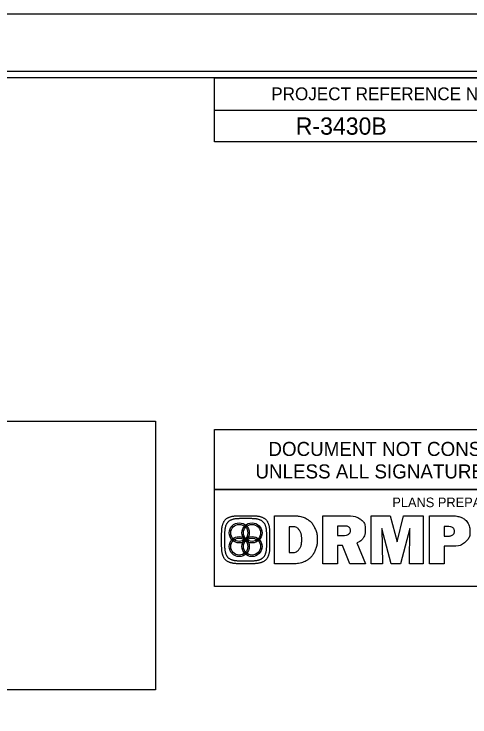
# Model space of a CAD drawing. Extents: x 1252282 to 1252460, y 733735 to 733845.
# Drawn here: x 1252421.03 to 1252438.88, y 733817 to 733844.5 of the extents above; entities that cross this region are included whole.
import ezdxf

# ---------------------------------------------------------------- set-up
doc = ezdxf.new("R2010")
doc.units = 0
for name, color, linetype in [('Default', 7, 'Continuous'), ('Pattern 1', 7, 'Continuous'), ('Pattern 2', 7, 'Continuous'), ('Scratch_Level_0', 7, 'Continuous'), ('Sheet Cutting Line CELL', 7, 'Continuous'), ('Sheet Data Field CELL', 7, 'Continuous'), ('Sheet Plot Border Inside CELL', 7, 'Continuous'), ('Sheet Plot Border Outside CELL', 7, 'Continuous'), ('Sheet Sticker Exception Certification CELL', 7, 'Continuous'), ('Sheet Typical CELL', 7, 'Continuous')]:
    doc.layers.add(name, color=color, linetype=linetype)

msp = doc.modelspace()

# ---------------------------------------------------------------- linework, layer by layer
at = {"layer": 'Default'}
msp.add_lwpolyline([(1252386.483, 733828.578), (1252426.564, 733828.578), (1252426.564, 733818.059), (1252386.483, 733818.059)], close=True, dxfattribs=at)
at = {"layer": 'Pattern 1'}
for p, q in [((1252429.822, 733824.875), (1252430.367, 733824.875)), ((1252435.01, 733822.994), (1252435.01, 733824.873)), ((1252435.01, 733824.873), (1252435.75, 733824.873)), ((1252435.75, 733824.873), (1252436.031, 733823.847)), ((1252436.031, 733823.847), (1252436.279, 733824.873)), ((1252436.279, 733824.873), (1252437.051, 733824.873)), ((1252437.051, 733824.873), (1252437.051, 733822.994)), ((1252430.334, 733824.76), (1252429.856, 733824.76)), ((1252435.796, 733822.994), (1252435.43, 733824.372)), ((1252435.43, 733824.372), (1252435.45, 733822.994)), ((1252436.518, 733824.372), (1252436.16, 733822.994)), ((1252436.509, 733822.994), (1252436.518, 733824.372)), ((1252429.156, 733823.663), (1252429.156, 733824.208)), ((1252429.271, 733824.175), (1252429.271, 733823.697)), ((1252430.919, 733823.697), (1252430.919, 733824.175)), ((1252431.034, 733824.208), (1252431.034, 733823.663)), ((1252430.367, 733822.997), (1252429.822, 733822.997)), ((1252429.856, 733823.112), (1252430.334, 733823.112)), ((1252435.45, 733822.994), (1252435.01, 733822.994)), ((1252436.16, 733822.994), (1252435.796, 733822.994)), ((1252437.051, 733822.994), (1252436.509, 733822.994))]:
    msp.add_line(p, q, dxfattribs=at)
for points in [[(1252431.925, 733822.994), (1252431.227, 733822.994), (1252431.227, 733824.873), (1252431.951, 733824.873)], [(1252434.45, 733823.815), (1252434.788, 733822.994), (1252434.171, 733822.994), (1252433.892, 733823.706), (1252433.695, 733823.706), (1252433.695, 733822.994), (1252433.123, 733822.994), (1252433.123, 733824.873), (1252434.041, 733824.873)], [(1252438.2, 733823.678), (1252437.867, 733823.678), (1252437.867, 733822.994), (1252437.291, 733822.994), (1252437.291, 733824.873), (1252438.092, 733824.873)], [(1252431.951, 733824.441), (1252431.803, 733824.441), (1252431.803, 733823.433), (1252431.933, 733823.433)], [(1252433.961, 733824.472), (1252433.695, 733824.472), (1252433.695, 733824.105), (1252433.969, 733824.105)], [(1252438.056, 733824.448), (1252437.867, 733824.448), (1252437.867, 733824.08), (1252438.022, 733824.08)]]:
    msp.add_lwpolyline(points, dxfattribs=at)
for points, degree in [([(1252429.156, 733824.208), (1252429.156, 733824.575), (1252429.456, 733824.875), (1252429.822, 733824.875)], 2), ([(1252430.367, 733824.875), (1252430.734, 733824.875), (1252431.034, 733824.575), (1252431.034, 733824.208)], 2), ([(1252431.951, 733824.873), (1252432.064, 733824.873), (1252432.166, 733824.863), (1252432.256, 733824.843), (1252432.346, 733824.822), (1252432.425, 733824.791), (1252432.492, 733824.749), (1252432.621, 733824.668), (1252432.721, 733824.556), (1252432.792, 733824.413), (1252432.863, 733824.271), (1252432.898, 733824.111), (1252432.898, 733823.934), (1252432.898, 733823.777), (1252432.867, 733823.63), (1252432.804, 733823.494), (1252432.742, 733823.357), (1252432.656, 733823.248), (1252432.549, 733823.167), (1252432.468, 733823.108), (1252432.378, 733823.064), (1252432.277, 733823.036), (1252432.176, 733823.008), (1252432.059, 733822.994), (1252431.925, 733822.994)], 3), ([(1252434.041, 733824.873), (1252434.287, 733824.873), (1252434.471, 733824.827), (1252434.594, 733824.736), (1252434.716, 733824.645), (1252434.778, 733824.507), (1252434.778, 733824.324), (1252434.778, 733824.197), (1252434.75, 733824.09), (1252434.694, 733824.003), (1252434.638, 733823.915), (1252434.556, 733823.853), (1252434.45, 733823.815)], 3), ([(1252438.092, 733824.873), (1252438.217, 733824.873), (1252438.321, 733824.865), (1252438.403, 733824.85), (1252438.486, 733824.834), (1252438.554, 733824.81), (1252438.609, 733824.776), (1252438.697, 733824.721), (1252438.764, 733824.651), (1252438.809, 733824.566), (1252438.855, 733824.481), (1252438.878, 733824.385), (1252438.878, 733824.278), (1252438.878, 733824.099), (1252438.815, 733823.954), (1252438.691, 733823.844), (1252438.567, 733823.733), (1252438.403, 733823.678), (1252438.2, 733823.678)], 3), ([(1252429.856, 733824.76), (1252429.534, 733824.76), (1252429.271, 733824.497), (1252429.271, 733824.175)], 2), ([(1252430.919, 733824.175), (1252430.919, 733824.497), (1252430.655, 733824.76), (1252430.334, 733824.76)], 2), ([(1252431.933, 733823.433), (1252432.041, 733823.433), (1252432.127, 733823.479), (1252432.192, 733823.572), (1252432.257, 733823.665), (1252432.29, 733823.788), (1252432.29, 733823.942), (1252432.29, 733824.095), (1252432.259, 733824.216), (1252432.198, 733824.306), (1252432.136, 733824.396), (1252432.054, 733824.441), (1252431.951, 733824.441)], 3), ([(1252433.969, 733824.105), (1252434.035, 733824.105), (1252434.09, 733824.122), (1252434.132, 733824.156), (1252434.175, 733824.19), (1252434.196, 733824.234), (1252434.196, 733824.288), (1252434.196, 733824.35), (1252434.176, 733824.396), (1252434.137, 733824.426), (1252434.098, 733824.457), (1252434.039, 733824.472), (1252433.961, 733824.472)], 3), ([(1252438.022, 733824.08), (1252438.099, 733824.08), (1252438.16, 733824.096), (1252438.203, 733824.128), (1252438.246, 733824.161), (1252438.268, 733824.206), (1252438.268, 733824.265), (1252438.268, 733824.324), (1252438.25, 733824.369), (1252438.214, 733824.401), (1252438.177, 733824.432), (1252438.125, 733824.448), (1252438.056, 733824.448)], 3), ([(1252429.822, 733822.997), (1252429.456, 733822.997), (1252429.156, 733823.297), (1252429.156, 733823.663)], 2), ([(1252429.271, 733823.697), (1252429.271, 733823.375), (1252429.534, 733823.112), (1252429.856, 733823.112)], 2), ([(1252430.334, 733823.112), (1252430.655, 733823.112), (1252430.919, 733823.375), (1252430.919, 733823.697)], 2), ([(1252431.034, 733823.663), (1252431.034, 733823.297), (1252430.734, 733822.997), (1252430.367, 733822.997)], 2)]:
    msp.add_open_spline(points, degree=degree, dxfattribs=at)
at = {"layer": 'Pattern 2'}
for centre, radius in [((1252429.845, 733824.203), 0.393), ((1252430.344, 733824.203), 0.393), ((1252429.845, 733824.203), 0.334), ((1252430.344, 733824.203), 0.334), ((1252429.845, 733823.669), 0.393), ((1252430.344, 733823.669), 0.393), ((1252429.845, 733823.669), 0.334), ((1252430.344, 733823.669), 0.334)]:
    msp.add_circle(centre, radius, dxfattribs=at)
at = {"layer": 'Scratch_Level_0'}
msp.add_lwpolyline([(1252448.882, 733825.897), (1252448.882, 733822.104), (1252428.878, 733822.104), (1252428.878, 733825.897)], close=True, dxfattribs=at)
at = {"layer": 'Sheet Cutting Line CELL'}
msp.add_line((1252450.583, 733844.502), (1252282.183, 733844.502), dxfattribs=at)
at = {"layer": 'Sheet Plot Border Inside CELL'}
msp.add_lwpolyline([(1252450.133, 733842.257), (1252283.483, 733842.257), (1252283.483, 733736.747), (1252450.133, 733736.747)], close=True, dxfattribs=at)
at = {"layer": 'Sheet Plot Border Outside CELL'}
msp.add_lwpolyline([(1252450.583, 733844.502), (1252282.183, 733844.502), (1252282.183, 733734.502), (1252450.583, 733734.502)], close=True, dxfattribs=at)
at = {"layer": 'Sheet Sticker Exception Certification CELL'}
for p, q in [((1252428.878, 733825.897), (1252428.878, 733828.247)), ((1252428.878, 733828.247), (1252448.882, 733828.247)), ((1252448.882, 733825.897), (1252428.878, 733825.897))]:
    msp.add_line(p, q, dxfattribs=at)
at = {"layer": 'Sheet Typical CELL'}
msp.add_line((1252428.878, 733840.747), (1252448.883, 733840.747), dxfattribs=at)
for points in [[(1252448.883, 733842.002), (1252298.883, 733842.002), (1252298.883, 733737.002), (1252448.883, 733737.002)], [(1252428.878, 733842.002), (1252448.883, 733842.002), (1252448.883, 733839.497), (1252428.878, 733839.497)]]:
    msp.add_lwpolyline(points, close=True, dxfattribs=at)

# ---------------------------------------------------------------- texts
at = {"layer": 'Pattern 2'}
msp.add_text('PLANS PREPARED BY:', height=0.375, rotation=360, dxfattribs=at).set_placement((1252435.838, 733825.21))
at = {"layer": 'Sheet Data Field CELL'}
msp.add_text('R-3430B  ', height=0.675, dxfattribs=at).set_placement((1252432.058, 733839.782))
at = {"layer": 'Sheet Sticker Exception Certification CELL'}
for s, p in [('DOCUMENT NOT CONSIDERED FINAL', (1252430.985, 733827.213)), ('UNLESS ALL SIGNATURES COMPLETED', (1252430.478, 733826.333))]:
    msp.add_text(s, height=0.55, dxfattribs=at).set_placement(p)
at = {"layer": 'Sheet Typical CELL'}
msp.add_text('PROJECT REFERENCE NO.', height=0.50001, dxfattribs=at).set_placement((1252431.098, 733841.132))

doc.saveas('drawing.dxf')
